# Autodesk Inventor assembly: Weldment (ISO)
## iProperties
Length Units: 11269
Angle Units: 11283
Time Units: 11279
Mass Units: 11290
Length Display Precision: 3
Angle Display Precision: 2
Part Number: Weldment (ISO)
Document SubType Name: Weldment
Created: 2002-06
Designer: smithga
Part Number: Ens_support_corps
Created: 2008-02
Designer: Pascal
Material: Aluminum soudé-6061
Control State: 0
Master: False
Shininess: 64.0
Angle Units: 11279
Time Units: 11290
Mass Units: 11283
Compacted: True
DESIGNATION: Ensemble support corps
Density: 0.0
Volumn: 0.0
Area: 0.0
PropertySet Name: Model Information
Author: Pascal
